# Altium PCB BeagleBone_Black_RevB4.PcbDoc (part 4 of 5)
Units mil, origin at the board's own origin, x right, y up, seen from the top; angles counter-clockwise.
Board outline 3401 x 2151 mil, 6 copper layers (TOP, LYR2_GND, LYR3, LYR4, LYR5_PWR, BOTTOM), stack 62 mil thick; 381 components, 310 nets, 1705 pads, 850 vias.
Unrouted connection lines stored in the file: 1.
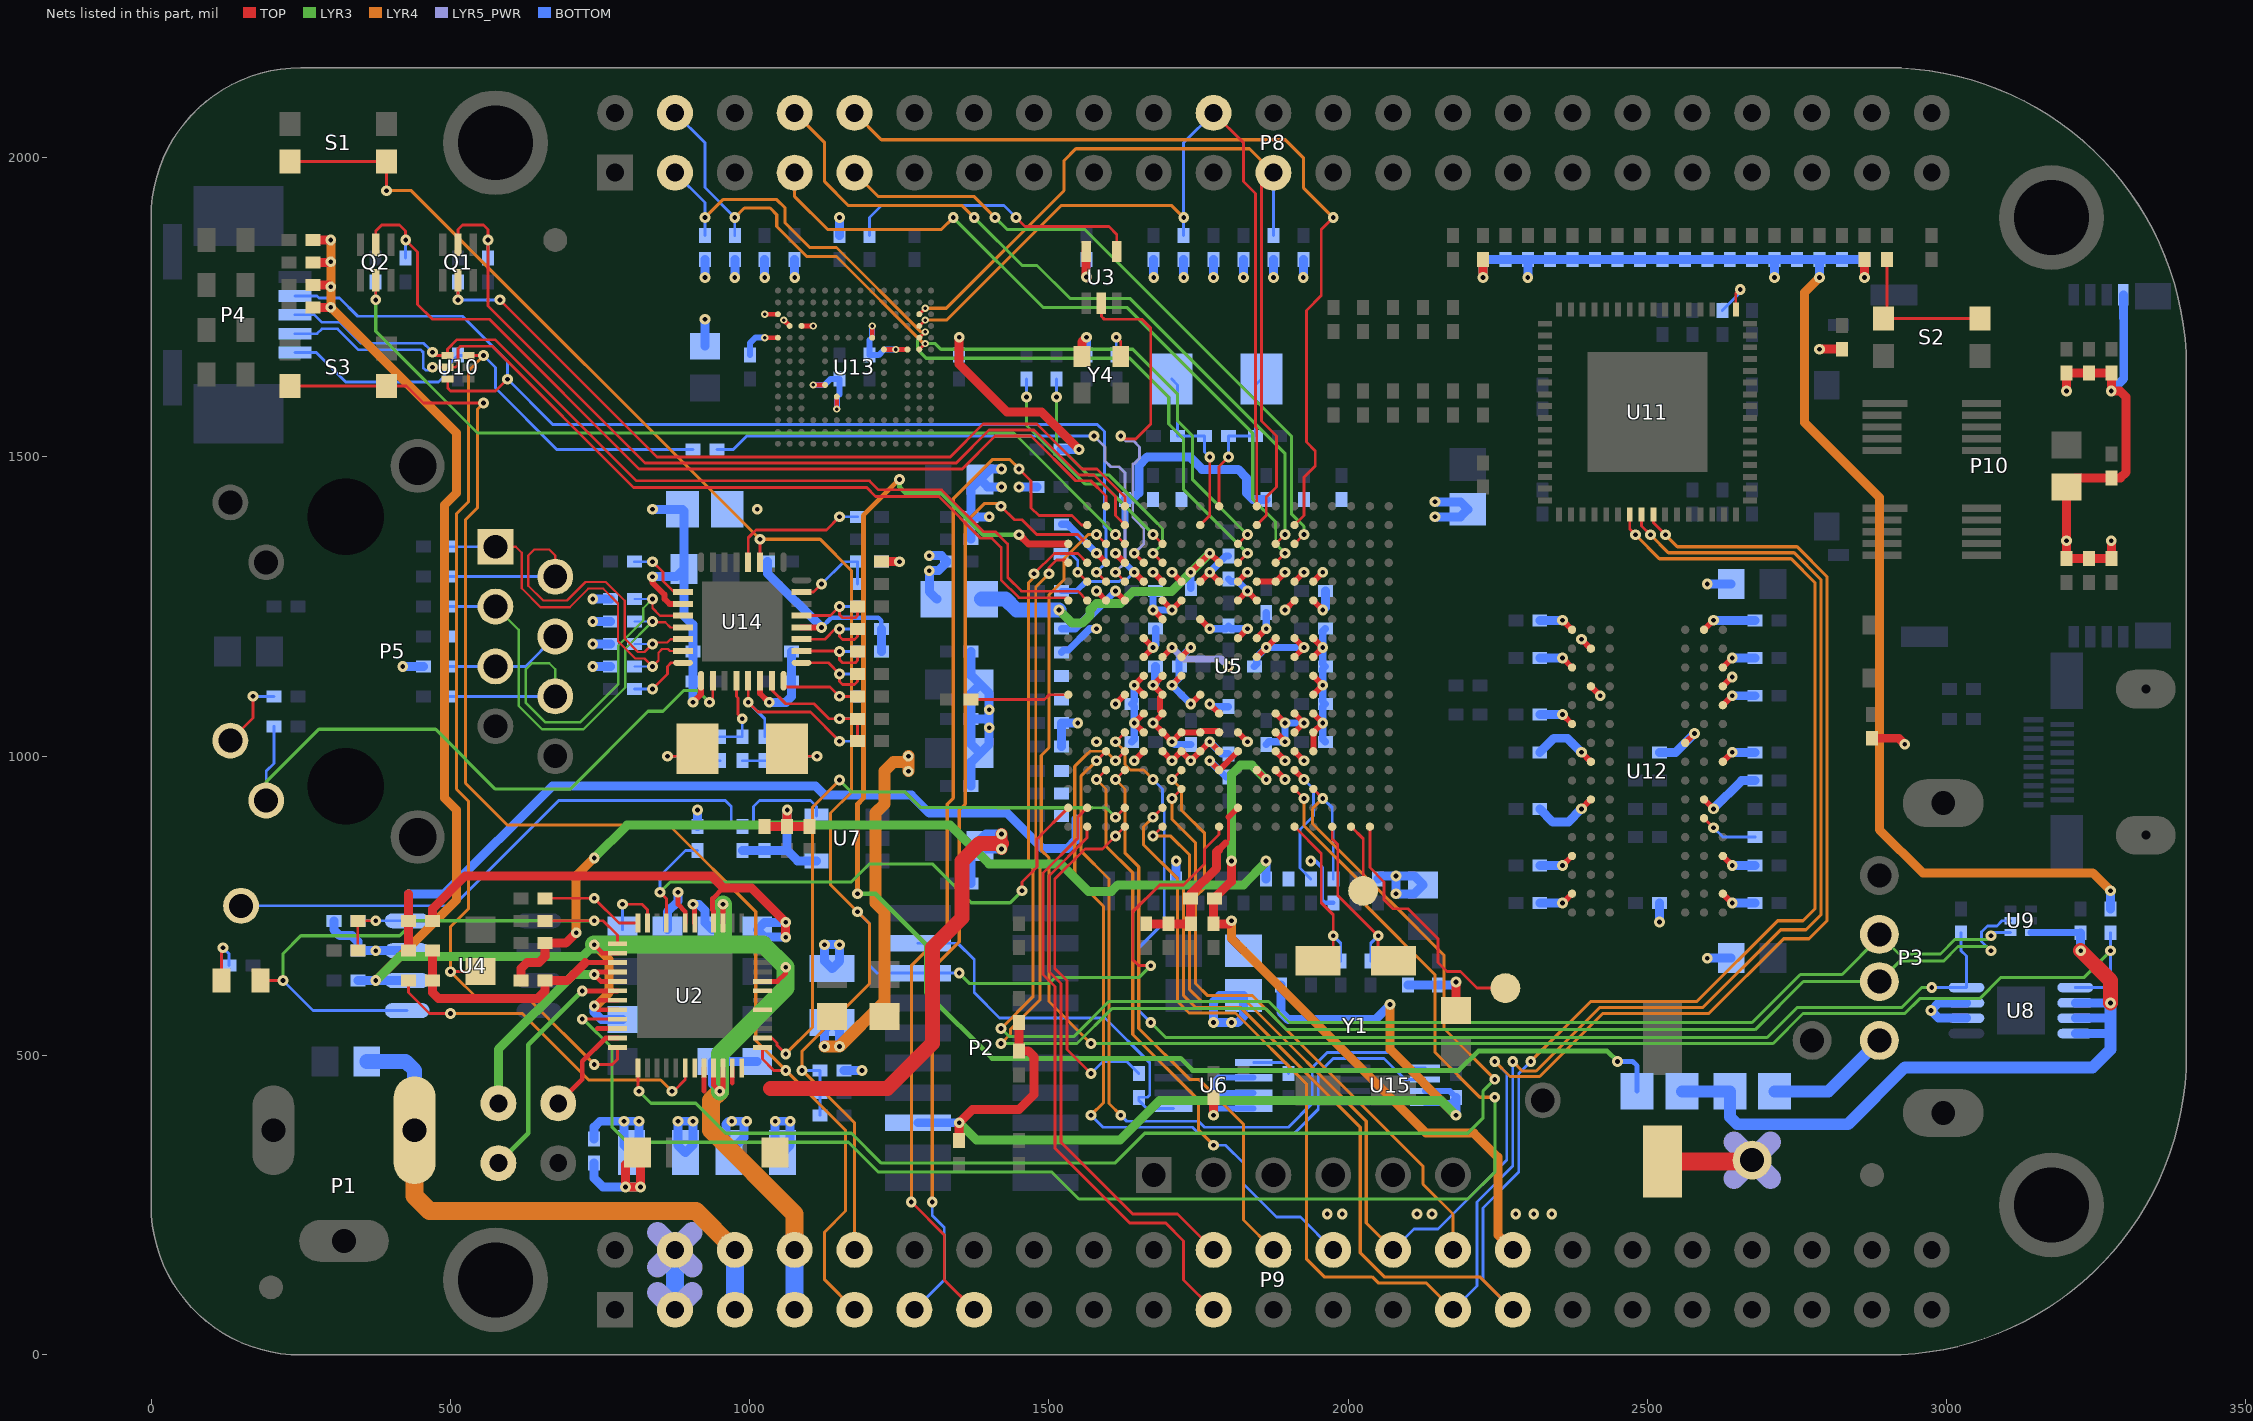
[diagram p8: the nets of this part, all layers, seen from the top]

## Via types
v1: diameter 18, hole 8, TOP to BOTTOM, tented both sides, 793 vias
v2: diameter 22, hole 12, TOP to BOTTOM, tented both sides, 30 vias
v3: diameter 12, hole 6, TOP to BOTTOM, tented both sides, 27 vias

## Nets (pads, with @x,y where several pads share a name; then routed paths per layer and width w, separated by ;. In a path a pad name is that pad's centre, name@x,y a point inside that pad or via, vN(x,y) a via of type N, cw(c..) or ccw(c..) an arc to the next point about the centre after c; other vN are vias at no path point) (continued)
MMC1_DAT4: P8.23 R105.2 U5.U8 U13.B3 | length 1478.1
  TOP w4.75: U13.B3@1283.27,1738.58 v3(1293.11,1748.43) ; U5.U8@1847.24,1386.22 1863.01,1401.99 1863.01,1433.01 1880,1450 1880,1535 1855,1560 1855,1955 P8.23@1875,1975
  LYR4 w5.25: v3(1293.11,1748.43) 1328.43,1748.43 1525,1945 1525,1995 1545,2015 1835,2015 P8.23@1875,1975
  BOTTOM w4.75: R105.2@1875,1870 P8.23@1875,1975
MMC1_DAT5: P8.22 R106.2 U5.V8 U13.B4 | length 1446.2
  TOP w4.75: U13.B4@1283.27,1718.9 v3(1293.11,1728.74) ; P8.22@1775,2075 1825,2025 1825,1960 1845,1940 1845,1550 1847.24,1547.76 U5.V8@1847.24,1417.72
  LYR4 w5.25: v3(1293.11,1728.74) 1328.74,1728.74 1520,1920 1705,1920 v1(1725,1900)
  BOTTOM w4.75: R106.2@1725,1870 v1(1725,1900) 1725,2025 P8.22@1775,2075
MMC1_DAT6: P8.3 R107.2 U5.R9 U13.B5 | length 1451.7
  TOP w4.75: U13.B5@1283.27,1699.21 v3(1293.11,1709.06) ; U5.R9@1815.75,1323.23 v1(1831.5,1338.98)
  LYR3 w5.25: v3(1293.11,1709.06) 1280,1695.95 1280,1680 1295,1665 1635,1665 1700,1600 1700,1555 1725,1530 1725,1445.48 v1(1831.5,1338.98)
  LYR4 w5.25: v1(925,1900) 955,1930 1045,1930 1059.01,1915.99 1059.01,1890.99 1100,1850 1145,1850 1285.94,1709.06 v3(1293.11,1709.06)
  BOTTOM w4.75: P8.3@875,1975 925,1925 v1(925,1900) R107.2@925,1870
MMC1_DAT7: P8.4 R108.2 U5.T9 U13.B6 | length 1452.6
  TOP w4.75: U13.B6@1283.27,1679.53 v3(1293.11,1689.37) ; U5.T9@1815.75,1354.72 v1(1831.5,1370.47)
  LYR3 w5.25: v3(1293.11,1689.37) 1310,1689.37 1319.37,1680 1640,1680 1715,1605 1715,1560 1740,1535 1740,1461.97 v1(1831.5,1370.47)
  LYR4 w5.25: v1(975,1900) 990.99,1915.99 1034.01,1915.99 1045,1905 1045,1885 1095,1835 1145,1835 1290.63,1689.37 v3(1293.11,1689.37)
  BOTTOM w4.75: P8.4@875,2075 925,2025 925,1950 v1(975,1900) R108.2@975,1870
MODE2: R113.1 R138.2 U14.15 | length 152
  TOP w4.75: U14.15@1086.5,1274.25 1106.75,1274.25 v1(1120,1287.5)
  BOTTOM w4.75: v1(1120,1287.5) 1157.5,1325 R113.1@1180,1325 R138.2@1180,1287.5
NetC19_1: C19.1 R10.1 R11.2 U4.4 | length 162.5
  TOP w4.75: R10.1@345,675 C19.1@345,725 v1(375,725)
  BOTTOM w4.75: R11.2@345,725 v1(375,725) U4.4@427.5,725
NetR21_1: R21.1 U6.5 | length 73.5
  BOTTOM w4.75: U6.5@1842,488.4 1895,488.4 1900,483.4 R21.1@1900,470
NetR75_2: R75.2 S2.1 S2.3 | length 262.3
  TOP w4.75: R75.2@2900,1830 2900,1737.21 S2.3@2894.29,1731.5 S2.1@3055.71,1731.5
NetR149_1: R149.1 U11.49 | length 84.2
  TOP w4.75: U11.49@2647.64,1746.26 2647.64,1772.64 v1(2655,1780)
  BOTTOM w4.75: R149.1@2625,1745 2655,1775 v1(2655,1780)
NetR159_2: R159.2 U5.P15 | length 925
  TOP w4.75: v1(1611,1307.5) U5.P15@1626.77,1291.73
  LYR5_PWR w4.75: v1(1575,1535) 1593.62,1516.38 1593.62,1493.22 1603.22,1483.62 1616.78,1483.62 1626.74,1473.66 1626.74,1323.24 v1(1611,1307.5)
  BOTTOM w4.75: R159.2@945,1512.5 972.5,1512.5 995,1535 v1(1575,1535)
NetR162_1: R162.1 U3.4 | length 499.9
  TOP w4.75: v1(1445,1900) 1460,1885 1600,1885 1613.09,1871.91 U3.4@1613.09,1843.31
  BOTTOM w4.75: R162.1@1200,1870 1200,1900 1220,1920 1425,1920 v1(1445,1900)
NetR167_1: R167.1 Y4.3 | length 65.1
  TOP w4.75: v1(1612.5,1700) 1620,1692.5 Y4.3@1620,1668
  BOTTOM w4.75: R167.1@1612.5,1670 v1(1612.5,1700)
NetTP5_1: TP5.1 U2.4 U2.5 | length 386.2
  TOP w8: U2.5@778.94,623.62 751.38,623.62 v1(740,635) 744.37,639.37 U2.4@778.94,639.37
  LYR3 w15: TP5.1@580,420 580,510 705,635 v1(740,635)
NetTP6_1: TP6.1 U2.6 | length 404.8
  TOP w8: v1(720,607.87) U2.6@778.94,607.87
  LYR3 w8: TP6.1@580,320 630,370 630,517.87 v1(720,607.87)
NetTP7_1: TP7.1 U2.11 | length 161.7
  TOP w8: TP7.1@680,420 720,460 720,490 759.13,529.13 U2.11@778.94,529.13
NetU3_2: U3.2 U5.R14 | length 593.9
  TOP w4.75: U3.2@1587.5,1756.69 1587.5,1734.75 1592.25,1730 1655,1730 1670,1715 1670,1555 1645,1530 1625,1530 v1(1620,1535) ; v1(1642.5,1339) U5.R14@1658.27,1323.23
  LYR5_PWR w4.75: v1(1620,1535) 1628.62,1526.38 1641.78,1526.38 1651.38,1516.78 1651.38,1498.22 1641.78,1488.62 1640,1488.62 1640,1400 1658.26,1381.74 1658.26,1354.76 v1(1642.5,1339)
OSC0_IN: C25.1 R17.1 U5.V10 Y2.2 | length 267.9
  TOP w4.75: U5.V10@1784.25,1417.72 1784.25,1484.25 v1(1800,1500)
  BOTTOM w4.75: v1(1800,1500) R17.1@1799.96,1535 C25.1@1845,1535 1845,1620.2 Y2.2@1854.8,1630
OSC0_OUT: C26.1 R17.2 U5.U11 Y2.1 | length 302.9
  TOP w4.75: U5.U11@1752.76,1386.22 1768.52,1401.98 v1(1768.52,1500)
  BOTTOM w4.75: Y2.1@1705.2,1630 1715,1620.2 C26.1@1715,1535 R17.2@1759.96,1535 1760,1508.52 v1(1768.52,1500)
OSC1_IN: C21.2 U5.A6 Y1.1 | length 318.6
  TOP w4.75: U5.A6@1910.24,882.28 1955,837.52 1955,755 1975,735 v1(1975,700) 1975,667.5 1965.7,658.2 Y1.1@1949.5,658.2
  BOTTOM w4.75: v1(1975,700) 1987.5,687.5 C21.2@1987.5,657.5
OSC1_OUT: C22.2 U5.A4 Y1.4 | length 323.6
  TOP w4.75: U5.A4@1973.23,882.28 1973.23,861.77 1982.5,852.5 1982.5,767.5 v1(2050,700) 2050,667.5 2059.3,658.2 Y1.4@2075.5,658.2
  BOTTOM w4.75: C22.2@2037.5,657.5 2037.5,687.5 v1(2050,700)
P_BYPASS: C4.2 U2.47 | length 110.2
  TOP w4.75: v1(787.5,752.5) 820,752.5 829.13,743.37 U2.47@829.13,721.06
  BOTTOM w4.75: C4.2@787.5,710 v1(787.5,752.5)
P_INT_LDO: C3.2 U2.48 | length 173.1
  TOP w4.75: C3.2@657.5,762.5 v1(740,762.5) 781.44,721.06 U2.48@813.39,721.06
P_L1: L1.1 U2.20 | length 179.3
  TOP w8: 923.62,440 U2.20@923.62,478.94
  BOTTOM w15: L1.1@880,350 v1(880,390) v1(905,390) 905,350 L1.1@892.5,337.5 L1.1@880,350
P_L2: L2.1 U2.23 | length 176.4
  TOP w8: 970.87,454.13 U2.23@970.87,478.94
  BOTTOM w15: L2.1@960,342.5 960,385 965,390 v1(970,390) v1(995,390) 990,385 990,362.5 L2.1@965,337.5 L2.1@960,342.5
P_L3: L3.1 U2.31 | length 115.4
  BOTTOM w15: L3.1@1125,657.5 v1(1125,685) v1(1150,685) 1150,657.5 L3.1@1137.5,645 L3.1@1125,657.5
PHY_VDDCR: C134.1 C136.1 U14.6 | length 159.6
  TOP w10: U14.6@1017.05,1126 1017.05,1104.83 1031.88,1090 v1(1032.5,1090)
  BOTTOM w15: v1(1032.5,1090) 1060.25,1090 1070,1099.75 C134.1@1070,1125 C136.1@1070,1175
PHY_XTAL1: C143.1 R141.2 R142.1 Y3.1 | length 183.5
  TOP w4.75: Y3.1@1062.3,1012.5 1074.8,1000 v1(1112.5,1000)
  BOTTOM w4.75: R141.2@987.5,992.5 R142.1@1025,992.5 C143.1@1062.5,992.5 1070,1000 v1(1112.5,1000)
PHY_XTAL2: R141.1 R143.1 U14.4 | length 135.1
  TOP w4.75: U14.4@977.65,1126 977.65,1099.85 980.15,1097.35 980.15,1069.85 v1(987.5,1062.5)
  BOTTOM w4.75: R143.1@950,1032.5 R141.1@987.5,1032.5 v1(987.5,1062.5)
PHYX: C142.1 R143.2 Y3.2 | length 146
  TOP w4.75: v1(862.5,1000) 900.2,1000 Y3.2@912.7,1012.5
  BOTTOM w4.75: v1(862.5,1000) 905,1000 C142.1@912.5,992.5 R143.2@950,992.5
PMIC_INT: R1.2 U2.45 U5.B18 | length 994.1
  TOP w4.75: v1(850,772.5) 860.63,761.87 U2.45@860.63,721.06 ; v1(1455,775) 1455,790 1480,815 1480,861.5 U5.B18@1532.28,913.78
  LYR3 w5.25: v1(850,772.5) 867.5,790 1170,790 1200,820 1305,820 1370,755 1435,755 v1(1455,775)
  BOTTOM w4.75: v1(850,772.5) 850,800 892.5,842.5 R1.2@912.5,842.5
PMIC_PGOOD: U2.26 U5.B15 | length 1056.1
  TOP w4.75: U2.26@1021.06,529.13 1037.35,529.13 1045.54,520.94 1045.54,516.96 v1(1060,502.5) ; v1(1611,898) U5.B15@1626.77,913.78
  LYR3 w4.75: 1572.64,913.74 1595.26,913.74 v1(1611,898)
  LYR3 w5.25: v1(1150,960) 1170,940 1260,940 1285.99,914.01 1413.74,914.01 1414.01,913.74 1572.64,913.74
  LYR4 w5.25: v1(1060,502.5) 1105,547.5 1105,915 v1(1150,960)
PMIC_POWR_EN: U2.9 U5.C6 | length 2598.3
  TOP w4.75: v1(720,560.63) U2.9@778.94,560.63 ; U5.C6@1910.24,945.28 v1(1926,929.5)
  LYR3 w5.25: v1(720,560.63) 721.87,560.63 770,512.5 770,380 795,355 1165,355 1215,305 1505,305 1550,260 2200,260 2245,305 v1(2245,430)
  LYR4 w5.25: v1(1926,929.5) 1926,884 2030,780 2030,750 2145,635 2145,505 2220,430 v1(2245,430)
PROC_A15: R18.1 U5.A15 | length 599.8
  TOP w4.75: v1(1570,470) 1530,510 1530,625 1509.51,645.49 1509.51,794.51 1560,845 1589.5,845 v1(1611,866.5) U5.A15@1626.77,882.28
  BOTTOM w4.75: v1(1570,470) 1590,490 1630,490 R18.1@1650,470
PWR_BUT: P9.9 S3.2 S3.4 U2.25 | length 2385.1
  TOP w4.75: S3.4@231.79,1618.5 S3.2@393.21,1618.5 426.5,1618.5 455,1590 v1(555,1590) ; U2.25@1021.06,513.39 1021.06,493.94 1040,475 v1(1060,475)
  LYR4 w5.25: v1(555,1590) 545,1580 545,1415 525,1395 525,955 595,885 865,885 1010,740 1010,525 v1(1060,475) 1160,375 1160,240 1125,205 1125,125 P9.9@1175,75
PWR_LEDR: D1.1 R12.2 | length 90.2
  TOP w4.75: D1.1@117.5,625 117.5,677.5 v1(120,680)
  BOTTOM w4.75: v1(120,680) 130,670 R12.2@130,650
RBIAS: R144.1 U14.32 | length 106.4
  TOP w4.75: v1(837.5,1112.5) 862.5,1137.5 862.5,1150 868.55,1156.05 U14.32@888.5,1156.05
  BOTTOM w4.75: R144.1@807.5,1112.5 v1(837.5,1112.5)
RCLKIN: R140.2 R142.2 U14.5 | length 314.4
  TOP w4.75: U14.5@997.35,1126 997.35,1100.15 997.5,1100 v1(997.5,1090) 1013.88,1073.62 1101.38,1073.62 v1(1150,1025)
  BOTTOM w4.75: v1(997.5,1090) 1025,1062.5 R142.2@1025,1032.5 ; v1(1150,1025) R140.2@1180,1025
REFCLKO: R118.1 R124.2 R131.2 U14.7 | length 246
  TOP w4.75: U14.7@1036.75,1126 1036.75,1110.75 1060,1087.5 1107.5,1087.5 1132.5,1062.5 v1(1150,1062.5) R124.2@1180,1062.5 R118.1@1180,1025
  BOTTOM w4.75: v1(1150,1062.5) R131.2@1180,1062.5
RXD0/MODE0: R112.1 R128.2 U14.11 | length 159.7
  TOP w4.75: U14.11@1086.5,1195.45 1125.45,1195.45 1142.5,1212.5 v1(1150,1212.5) 1150,1200 1155,1195 1175,1195 1180,1200 R128.2@1180,1212.5
  BOTTOM w4.75: v1(1150,1212.5) R112.1@1180,1212.5
RXD1/MODE1: R114.1 R127.2 U14.10 | length 156.2
  TOP w4.75: U14.10@1086.5,1175.75 1137.5,1175.75 1149.39,1175.61 v1(1150,1175) 1150,1161.23 1155,1156.23 1176.23,1156.23 1180,1160 R127.2@1180,1175
  BOTTOM w4.75: v1(1150,1175) R114.1@1180,1175
RXD2/RMIISEL: R117.1 R126.2 U14.9 | length 160.3
  TOP w4.75: U14.9@1086.5,1156.05 1131.45,1156.05 v1(1150,1137.5) 1150,1125 1155,1120 1175,1120 1180,1125 R126.2@1180,1137.5
  BOTTOM w4.75: v1(1150,1137.5) R117.1@1180,1137.5
RXD3/PHYAD2: R116.1 R125.2 U14.8 | length 167.4
  TOP w4.75: U14.8@1056.45,1126 1056.45,1120.74 1061.45,1115.74 1134.26,1115.74 v1(1150,1100) R125.2@1180,1100
  BOTTOM w4.75: v1(1150,1100) R116.1@1180,1100
RXDV: R129.2 U14.26 | length 110.8
  TOP w4.75: v1(837.5,1325) 855,1307.5 855,1292.5 873.25,1274.25 U14.26@888.5,1274.25
  BOTTOM w4.75: R129.2@807.5,1325 v1(837.5,1325)
RXER/PHYAD0: R115.1 R133.2 U14.13 | length 162.2
  TOP w4.75: U14.13@1086.5,1234.85 1134.85,1234.85 v1(1150,1250) 1150,1236.23 1155,1231.23 1176.23,1231.23 1180,1235 R133.2@1180,1250
  BOTTOM w4.75: v1(1150,1250) R115.1@1180,1250
RXN: C138.1 P5.2 R121.1 U14.30 | length 724.8
  TOP w3.75: P5.2@675,1300 675,1335.39 665,1345.39 640,1345.39 630,1335.39 630,1285 655,1260 694.44,1260 725.44,1291 759.56,1291 791,1259.56 791,1196.5 813.25,1174.25 824.25,1174.25 v1(837.5,1187.5) 840,1190 862.05,1190 867.5,1195.45 U14.30@888.5,1195.45
  BOTTOM w3.75: R121.1@807.5,1187.5 v1(837.5,1187.5)
  BOTTOM w4.75: C138.1@495,1300 P5.2@675,1300
RXP: C137.1 P5.1 R120.1 U14.31 | length 624.8
  TOP w3.75: P5.1@575,1350 609,1350 619,1340 619,1280.44 650.44,1249 699,1249 730,1280 755,1280 780,1255 780,1191.94 808.69,1163.25 824.25,1163.25 v1(837.5,1150) 847.5,1160 847.5,1173 853.5,1179 863.5,1179 866.75,1175.75 U14.31@888.5,1175.75
  BOTTOM w3.75: R120.1@807.5,1150 v1(837.5,1150)
  BOTTOM w4.75: C137.1@495,1350 P5.1@575,1350
SPI1_CS0: P9.28 U5.C12 U11.25 | length 2996.8
  TOP w4.75: v1(1705.5,929.5) U5.C12@1721.26,945.28 ; U11.25@2509.84,1403.74 2509.84,1390.16 v1(2530,1370)
  LYR4 w5.25: v1(1705.5,929.5) 1705.5,894.5 1745,855 1745,785 1735,775 1735,610 1755,590 1830,590 2030,390 2030,220 P9.28@2075,175 ; v1(2245,490) 2270.24,464.76 2319.76,464.76 2425,570 2602.5,570 2727.5,695 2770,695 2800,725 2800,1300 2750,1350 2550,1350 v1(2530,1370)
  BOTTOM w4.75: P9.28@2075,175 2110,210 2150.01,210 2265,324.99 2265,470 v1(2245,490)
SPI1_D0: P9.29 U5.B13 U11.24 | length 3207.4
  TOP w4.75: v1(1674,898) U5.B13@1689.76,913.78 ; U11.24@2490.16,1403.74 2490.16,1384.84 v1(2505,1370)
  LYR4 w5.25: v1(1674,898) 1658.01,882.01 1658.01,851.99 1715,795 1715,590 1734.01,570.99 1811.62,570.99 1930,452.61 1930,160 1960,130 2040,130 2050,120 2130,120 P9.29@2175,75 ; v1(2275,490) 2290.99,474.01 2314.01,474.01 2420,580 2592.5,580 2722.5,710 2765,710 2790,735 2790,1295 2745,1340 2535,1340 v1(2505,1370)
  BOTTOM w4.75: P9.29@2175,75 2215,115 2215,255 2275,315 v1(2275,490)
SPI1_D1: P9.30 U5.D12 | length 1059.3
  TOP w4.75: v1(1705.5,961) U5.D12@1721.26,976.77
  LYR4 w4.75: v1(1705.5,961) 1721.24,945.26 1721.24,910
  LYR4 w5.25: 1721.24,910 1760,871.24 1760,780 1744.75,764.75 1744.75,620.25 1765,600 1840,600 2125,315 2125,285 2175,235 P9.30@2175,175
SPI1_SCLK: P9.31 U5.A13 U11.23 | length 3191.3
  TOP w4.75: v1(1674,866.5) U5.A13@1689.76,882.28 ; U11.23@2470.47,1403.74 2470.47,1379.53 v1(2480,1370)
  LYR4 w5.25: v1(1674,866.5) 1703.5,866.5 1735,835 1735,795 1725,785 1725,600 1744.76,580.24 1819.76,580.24 2020,380 2020,170 2060,130 2220,130 P9.31@2275,75 ; v1(2305,490) 2405,590 2582.5,590 2717.5,725 2760,725 2780,745 2780,1290 2740,1330 2520,1330 v1(2480,1370)
  BOTTOM w4.75: P9.31@2275,75 2225,125 2225,245 2285,305 2285,470 v1(2305,490)
SYS_5V: C7.2 C8.2 C10.2 C13.2 C17.1 C34.1 P9.7 P9.8 R71.1 R72.1 R73.1 R74.1 RT1.1 U2.2 U2.7 U2.8 U2.21 U2.22 U2.32 U2.39 U2.42 U4.2 U8.2 U8.3 | length 4290.6
  TOP w8: v1(740,685) 754.13,670.87 U2.2@778.94,670.87 ; U2.8@778.94,576.38 746.12,576.38 v1(740,582.5) 749.63,592.13 U2.7@778.94,592.13 ; v1(905,752.5) 907.87,748.08 U2.42@907.87,721.06 ; U2.21@939.37,478.94 939.37,450.63 v1(950,440) 955.12,445.12 U2.22@955.12,478.94 ; U2.39@955.12,721.06 v1(955.12,752.5) ; U2.32@1021.06,623.62 1046.12,623.62 1060,637.5 v1(1060,647.5)
  TOP w15: R71.1@270,1750 v1(300,1750) ; R74.1@270,1787.5 296.97,1787.5 v1(300,1784.47) ; R73.1@270,1825 298.81,1825 v1(300,1826.19) ; R72.1@270,1862.5 v1(300,1862.5)
  TOP w30: C34.1@2525,322.5 2672.5,322.5 RT1.1@2675,325
  LYR3 w15: v1(375,625) 415,665 720,665 v1(740,685)
  LYR3 w30: v1(740,685) 955.12,685 ; v1(950,440) 950,502.5 1060,612.5 v1(1060,647.5) 1022.5,685 955.12,685 ; v1(955.12,752.5) 955.12,685
  LYR4 w15: v1(300,1862.5) v1(300,1826.19) v1(300,1784.47) v1(300,1750) 510,1540 510,1440 490,1420 490,930 510,910 510,760 v1(375,625) ; v1(740,582.5) 742.5,582.5 765,605 765,660 v1(740,685)
  LYR4 w30: v1(950,440) 935,425 935,375 1075,235 P9.8@1075,175
  LYR5_PWR w35: 2644.35,294.35 RT1.1@2675,325 ; 2644.35,355.65 RT1.1@2675,325 ; 2705.65,294.35 RT1.1@2675,325 ; 2705.65,355.65 RT1.1@2675,325
  BOTTOM w15: C17.1@345,625 v1(375,625) U4.2@427.5,625 ; v1(740,582.5) 740,572.5 752.5,560 C10.2@787.5,560 ; v1(905,752.5) 915,752.5 925,742.5 925,722.5 C13.2@937.5,710 955.12,727.62 v1(955.12,752.5) ; v1(950,440) 937.5,452.5 C7.2@937.5,490 C8.2@1012.5,490 ; U8.2@3032.9,562.2 2986.7,562.2 v1(2973.9,575) 2986.7,587.8 U8.3@3032.9,587.8
  BOTTOM w30: P9.7@1075,75 P9.8@1075,175
SYS_RESETN: C24.1 C30.1 P2.15 P9.10 R14.2 S1.2 S1.4 U5.A10 U14.19 | length 3585.2
  TOP w4.75: S1.4@231.79,1993.5 S1.2@393.21,1993.5 v1(393.21,1945) ; U14.19@1017.05,1324 v1(1017.05,1362.5) ; v1(1670,650) 1650,650 1640,660 1640,740 1685,785 1725,785 1760,820 1760,845 1784.25,869.25 U5.A10@1784.25,882.28
  LYR3 w5.25: v1(1350,637.5) 1367.5,620 1500,620 1510,630 1650,630 v1(1670,650)
  LYR4 w5.25: v1(393.21,1945) 434.55,1945 v1(1017.05,1362.5) 1117.52,1362.5 1170,1310 1170,940 1135,905 1135,785 v1(1180,740) 1200,720 1200,620 1087.5,507.5 v1(1087.5,475) 1175,387.5 P9.10@1175,175
  BOTTOM w4.75: v1(1087.5,475) R14.2@1117.5,475 C24.1@1117.5,437.5 C30.1@1117.5,400 ; v1(1180,740) 1200,720 1200,650 1212.5,637.5 P2.15@1281,637.5 v1(1350,637.5)
TCT_RCT: C141.1 P5.4 P5.5 R137.1 | length 250.7
  BOTTOM w4.75: C141.1@495,1200 R137.1@495,1150 P5.5@575,1150 625,1150 P5.4@675,1200
TESTOUT: TP3.1 U5.A3 | length 115.7
  TOP w4.75: U5.A3@2004.72,882.28 2025,862 TP3.1@2025,775
TIMER4: P8.7 U5.R7 | length 1231.1
  TOP w4.75: U5.R7@1878.74,1323.23 v1(1894.5,1339)
  LYR3 w4.75: 1878.76,1380 1878.76,1354.74 v1(1894.5,1339)
  LYR3 w5.25: v1(1340,1900) 1490,1750 1630,1750 1840.5,1539.5 1840.5,1429.5 1878.76,1391.24 1878.76,1380
  LYR4 w5.25: P8.7@1075,1975 1075,1935 1130,1880 1320,1880 v1(1340,1900)
TIMER5: P8.9 U5.T6 | length 1107.8
  TOP w4.75: U5.T6@1910.24,1354.72 v1(1926,1370.5)
  LYR3 w5.25: v1(1410,1900) 1430,1880 1560,1880 1905,1535 1905,1405 1926,1384 v1(1926,1370.5)
  LYR4 w5.25: P8.9@1175,1975 1215,1935 1375,1935 v1(1410,1900)
TIMER6: P8.10 U5.U6 | length 1454.8
  TOP w4.75: U5.U6@1910.24,1386.22 1925.97,1401.95 1925.97,1465.97 1945,1485 1945,1510 1930,1525 1930,1745 1955,1770 1955,1880 v1(1975,1900)
  LYR4 w5.25: P8.10@1175,2075 1220,2030 1895,2030 1925,2000 1925,1950 v1(1975,1900)
TIMER7: P8.8 U5.T7 | length 1250.8
  TOP w4.75: U5.T7@1878.74,1354.72 v1(1894.5,1370.5)
  LYR3 w5.25: v1(1375,1900) 1455,1820 1480,1820 1535,1765 1635,1765 1894.5,1505.5 v1(1894.5,1370.5)
  LYR4 w5.25: P8.8@1075,2075 1125,2025 1125,1960 1165,1920 1355,1920 v1(1375,1900)
TXCLK: R134.2 U14.20 | length 238.2
  TOP w4.75: U14.20@997.35,1324 997.35,1365.06 1010.53,1378.24 1128.24,1378.24 v1(1150,1400)
  BOTTOM w4.75: v1(1150,1400) R134.2@1180,1400
TXN: C140.1 P5.6 R123.1 U14.28 | length 799.6
  TOP w3.75: v1(837.5,1262.5) 837.5,1247.46 850.11,1234.85 U14.28@888.5,1234.85
  LYR3 w4: P5.6@675,1100 675,1145.2 665,1155.2 636,1155.2 626,1145.2 626,1089 658,1057 717,1057 780,1120 780,1184.48 822.14,1226.62 822.14,1247.14 v1(837.5,1262.5)
  BOTTOM w3.75: R123.1@807.5,1262.5 v1(837.5,1262.5)
  BOTTOM w4.75: C140.1@495,1100 P5.6@675,1100
TXP: C139.1 P5.3 R122.1 U14.29 | length 699.6
  TOP w3.75: v1(837.5,1225) 837.49,1224.3 837.94,1223.85 858.8,1223.85 867.5,1215.15 U14.29@888.5,1215.15
  LYR3 w4: P5.3@575,1250 614,1211 614,1084.02 653.02,1045 721.98,1045 792,1115.02 792,1179.5 v1(837.5,1225)
  BOTTOM w3.75: R122.1@807.5,1225 v1(837.5,1225)
  BOTTOM w4.75: C139.1@495,1250 P5.3@575,1250
U5_H18: R28.1 U5.H18 | length 165.5
  TOP w4.75: R28.1@1370,1095 1492.24,1095 1500,1102.76 U5.H18@1532.28,1102.76
U5_R13: R160.1 U5.R13 | length 413.8
  TOP w4.75: v1(1673.99,1339) U5.R13@1689.76,1323.23
  LYR3 w4.75: v1(1673.99,1339) 1689.76,1354.77 1689.76,1380.24 1675,1395
  LYR3 w5.25: v1(1512.5,1600) 1512.5,1522.5 1565,1470 1600,1470 1675,1395
  BOTTOM w4.75: v1(1512.5,1600) R160.1@1512.5,1630
U5_T13: R161.1 U5.T13 | length 387
  TOP w4.75: v1(1674,1370.5) U5.T13@1689.76,1354.72
  LYR3 w5.25: v1(1462.5,1600) 1462.5,1552.5 1560,1455 1590,1455 1674,1371 v1(1674,1370.5)
  BOTTOM w4.75: v1(1462.5,1600) R161.1@1462.5,1630
UART0_RX: U5.E15 U15.6 | length 1390.8
  TOP w4.75: v1(1611,992.5) U5.E15@1626.77,1008.27
  LYR4 w4.75: 1565,1005 1568.24,1008.24 1595.26,1008.24 v1(1611,992.5)
  LYR4 w5.25: 1565,1005 1543.01,983.01 1543.01,796.99 1590.99,749.01 1590.99,421.03 v1(1570,400.04)
  BOTTOM w4.75: v1(1570,400.04) 1590,380 1740,380 1750,370 1910,370 1950,410 1950,470 1975,495 2060,495 2095.2,459.8 U15.6@2128,459.8
UART0_TX: U5.E16 U15.5 | length 1267.1
  TOP w4.75: v1(1579.5,992.5) U5.E16@1595.28,1008.27
  LYR4 w5.25: v1(1579.5,992.5) 1553.26,966.26 1553.26,841.74 1600.24,794.76 1600.24,419.76 v1(1620,400)
  BOTTOM w4.75: v1(1620,400) 1630,390 1750,390 1760,380 1900,380 1940,420 1940,480 1965,505 2070,505 2095.5,479.5 U15.5@2128,479.5
UART1_RXD: P9.26 U5.D16 | length 1007.3
  TOP w4.75: v1(1579.5,961) U5.D16@1595.28,976.77
  LYR4 w4.75: v1(1579.5,961) 1595.24,945.26 1595.24,855.24
  LYR4 w5.25: 1595.24,855.24 1595.24,849.76 1640,805 1640,535 1750,425 1750,375 v1(1775,350)
  BOTTOM w4.75: v1(1775,350) 1795,350 1825,320 1825,285 1880,230 1920,230 P9.26@1975,175
UART1_TXD: P9.24 U5.D15 | length 926.4
  TOP w4.75: v1(1611,961) U5.D15@1626.77,976.77
  LYR4 w4.75: v1(1611,961) 1626.74,945.26 1626.74,920
  LYR4 w5.25: 1626.74,920 1627.26,919.48 1627.26,837.74 1650,815 1650,545 1735,460 1750,460 1825,385 1825,225 P9.24@1875,175
UART2_RXD: P9.22 U5.A17 | length 891.7
  TOP w4.75: 1563.76,873.02 1563.76,863.76 1499.76,799.76 1499.76,640.24 1520,620 1520,355 1640,235 1715,235 P9.22@1775,175 ; 1563.78,873.04 U5.A17@1563.78,882.28
UART2_TXD: P9.21 U5.B17 | length 1022.5
  TOP w4.75: U5.B17@1563.78,913.78 1548.01,898.01 1548.01,863.01 1490,805 1490,635 1510,615 1510,345 1635,220 1695,220 1725,190 1725,125 P9.21@1775,75
UART4_RXD: P9.11 U5.T17 | length 1612.1
  TOP w4.75: v1(1420,1417.5) 1442.5,1395 1455,1395 1479.55,1370.45 1548.05,1370.45 U5.T17@1563.78,1354.72
  LYR4 w5.25: v1(1305,255) 1305,645 1350,690 1350,910 1360,920 1360,1390 1392.5,1422.5 1415,1422.5 v1(1420,1417.5)
  BOTTOM w4.75: P9.11@1275,75 1325,125 1325,212.5 1305,232.5 v1(1305,255)
UART4_TXD: P9.13 U5.U17 | length 1750.4
  TOP w4.75: v1(1270,255) 1325,200 1325,125 P9.13@1375,75 ; v1(1450,1480) 1470,1460 1470,1415 1483.05,1401.95 1538.65,1401.95 1554.38,1386.22 U5.U17@1563.78,1386.22
  LYR4 w5.25: v1(1270,255) 1270,650 1330,710 1330,920 1340,930 1340,1430 1405.99,1495.99 1434.01,1495.99 v1(1450,1480)
USB0_DM: P4.2 U5.N18 U10.2 | length 1580
  TOP w4.5: v1(470,1650) U10.2@495.22,1650 508.5,1650 512.5,1654 512.5,1680.57 516.93,1685 570,1685 806,1449 1195.44,1449 1210.44,1434 1316,1434 1386,1364 1405,1364 1420,1349 1420,1294.44 1449.6,1264.84 1527.68,1264.84 U5.N18@1532.28,1260.24
  BOTTOM w4.5: P4.2@240,1706 277,1706 285,1714 311,1714 346,1679 450.39,1679 454.39,1675 454.39,1649 458.39,1645 466,1645 470,1649 v1(470,1650)
USB0_DP: P4.3 U5.N17 U10.1 | length 1582.2
  TOP w4.5: v1(470,1675) 475.32,1669.68 U10.1@495.22,1669.68 495,1669.9 495,1680 511,1696 574.56,1696 810.56,1460 1200,1460 1215,1445 1320.56,1445 1390.56,1375 1410.56,1375 1431,1354.56 1431,1299 1454.16,1275.84 1548.18,1275.84 U5.N17@1563.78,1260.24
  BOTTOM w4.5: P4.3@240,1737.5 272.5,1737.5 285,1725 315.56,1725 350.56,1690 454.95,1690 v1@465.39,1679.56 ; v1@465.44,1679.56 v1(470,1675)
USB0_ID: P4.4 U5.P16 U10.3 | length 1854.3
  TOP w4.75: U10.3@495.22,1630.32 495.22,1615 500.22,1610 575,1610 v1(595,1630) ; v1(1579.5,1307.5) U5.P16@1595.28,1291.73
  BOTTOM w4.75: P4.4@240,1769 276.74,1769 280,1765.74 314.26,1765.74 345,1735 520,1735 595,1660 v1(595,1630) 670.74,1554.26 1580.74,1554.26 1592.5,1542.5 1592.5,1382.5 1595.24,1379.76 1595.24,1323.24 v1(1579.5,1307.5)
USB1_DM: P3.2 U5.R18 U9.2 | length 2720.4
  TOP w4.5: v1(1500,1305) 1500,1315.03 1512.8,1327.83 1527.68,1327.83 U5.R18@1532.28,1323.23
  LYR3 w5: v1(1420,520) 1546.98,520 1604.98,578 1862,578 1897,543 2679.98,543 2760.38,623.4 P3.2@2887.5,623.4 2921.6,657.5 2994.48,657.5 3018.98,682 3066.9,682 v1(3073.9,675)
  LYR4 w5: v1(1420,520) 1435.86,535.86 1435.86,543.88 1485,593.02 1485,817.86 1477.86,825 1477.86,1282.86 v1(1500,1305)
  BOTTOM w4.5: v1(3073.9,675) 3058.29,690.61 3058.29,706.47 3068.14,716.32 3083.9,716.32 3092.58,725 U9.2@3106.62,725
USB1_DP: P3.3 U5.R17 U9.1 | length 2720.6
  TOP w4.5: v1(1475,1305) 1508.83,1338.83 1548.18,1338.83 U5.R17@1563.78,1323.23
  LYR3 w5: v1(1420,545) 1433,532 1542,532 1600,590 1866.98,590 1901.98,555 2675,555 2755.4,635.4 2825.4,635.4 2887.5,697.5 P3.3@2887.5,702.2 2920.2,669.5 2989.5,669.5 3014,694 3067.9,694 v1(3073.9,700)
  LYR4 w5: v1(1420,545) 1473,598 1473,812.88 1465.86,820.02 1465.86,1290 1475,1299.14 v1(1475,1305)
  BOTTOM w4.5: v1(3073.9,700) 3079.22,705.32 U9.1@3106.62,705.32
USB1_DRVVBUS: R53.1 U5.F15 U8.4 | length 2067.1
  TOP w4.75: v1(1611,1024) U5.F15@1626.77,1039.76
  LYR3 w5.25: v1(1670,555) 1695,530 2700,530 2750,580 2925,580 2958.4,613.4 v1(2975,613.4)
  LYR4 w4.75: v1(1611,1024) 1626.74,1008.26 1626.74,985.98 1635.98,976.74 1658.26,976.74 v1(1674,961)
  BOTTOM w4.75: v1(1670,555) 1650,575 1650,680 1692.5,722.5 1692.5,910 1689.76,912.74 1689.76,945.24 v1(1674,961) ; v1(2975,613.4) U8.4@3032.9,613.4 3032.9,666 3023.9,675 R53.1@3023.9,705
USB1_ID: R49.2 U5.P17 | length 74.2
  TOP w4.75: v1(1548,1307.5) 1550,1305.51 U5.P17@1563.78,1291.73
  BOTTOM w4.75: R49.2@1520,1337.5 1537.5,1337.5 1548,1327 v1(1548,1307.5)
USB1_OCN: R52.2 U5.T16 U8.5 | length 2865.6
  TOP w4.75: v1(1579.5,1370.5) U5.T16@1595.28,1354.72
  LYR3 w5.25: v1(1570,520) 2710,520 2760,570 2930,570 2955,595 3055,595 3090,630 3228.9,630 v1(3273.9,675)
  LYR4 w5.25: v1(1570,520) 1500,590 1500,830 1486.99,843.01 1486.99,1001.24 1500,1014.25 1500,1270 1525,1295 1525,1330 1565.5,1370.5 v1(1579.5,1370.5)
  BOTTOM w4.75: U8.5@3214.9,613.4 3262.3,613.4 3273.9,625 v1(3273.9,675) R52.2@3273.9,705
USB1_PWR: C35.1 FB7.1 FB8.2 U8.6 U8.7 U8.8 U9.6 | length 1290.4
  TOP w25: v1(3223.9,675) 3273.6,625.3 v1(3273.6,587.8)
  BOTTOM w12: U9.6@3141.18,705.32 3223.58,705.32 C35.1@3223.9,705
  BOTTOM w15: U8.8@3214.9,536.6 3273.6,536.6 ; U8.7@3214.9,562.2 3273.6,562.2 ; U8.6@3214.9,587.8 v1(3273.6,587.8) ; v1(3223.9,675) C35.1@3223.9,705
  BOTTOM w20: FB8.2@2557.4,440 FB7.1@2637.6,440 2637.6,397.4 2650,385 2835,385 2930,480 3243.9,480 3273.6,509.7 3273.6,536.6 3273.6,562.2 v1(3273.6,587.8)
USB1_VBUS: FB8.1 U5.T18 | length 2593.5
  TOP w12: v1(1450,1370) 1450.28,1370 1465.56,1354.72 U5.T18@1532.28,1354.72
  LYR3 w8: v1(1180,770) 1210,770 1295,685 1295,605 1405,495 1720,495 1740,475 2185,475 2217.36,507.36 2432.64,507.36 v1(2450,490) ; v1(1250,1462.5) 1250,1450 1260,1440 1320,1440 1390,1370 v1(1450,1370)
  LYR4 w8: v1(1180,770) 1180,920 1190,930 1190,1402.5 v1(1250,1462.5)
  BOTTOM w8: v1(2450,490) 2475,490 2482.6,482.4 FB8.1@2482.6,440
USB_DC: C1.2 C36.1 P4.1 R159.1 U2.12 U10.6 | length 2307.3
  TOP w4.75: v1(500,640) C1.2@550,640 ; U10.6@529.78,1669.68 554.68,1669.68 v1(555,1669.36) ; v1(740,485) 770.25,485 778.94,493.69 U2.12@778.94,513.39
  LYR4 w5.25: v1(555,1669.36) 530,1644.36 530,1425 510,1405 510,945 530,925 530,745 500,715 v1(500,640) 550,590 635,590 v1(740,485)
  BOTTOM w4.75: P4.1@240,1674.51 275.49,1674.51 325,1625 480,1625 490,1635 490,1647.5 C36.1@512.5,1670 512.82,1669.68 554.68,1669.68 v1(555,1669.36) 575,1649.36 575,1615 677.5,1512.5 R159.1@905,1512.5
USR0: Q1.2 R76.1 U5.V15 | length 1374.7
  TOP w4.75: v1(512.5,1762.5) Q1.2@512.5,1795.47 ; v1(582.5,1762.5) 845,1500 1335,1500 1390,1555 1480,1555 1555,1480 1580,1480 1626.77,1433.23 U5.V15@1626.77,1417.72
  BOTTOM w4.75: R76.1@512.5,1792.5 v1(512.5,1762.5) v1(582.5,1762.5)
USR1: Q1.5 R77.1 U5.U15 | length 1519.5
  TOP w4.75: Q1.5@512.5,1854.53 512.5,1880 520,1887.5 555,1887.5 562.5,1880 v1(562.5,1862.5) 562.5,1752.5 825,1490 1345,1490 1400,1545 1475,1545 1550,1470 1575,1470 1611.01,1433.99 1611.01,1401.98 U5.U15@1626.77,1386.22
  BOTTOM w4.75: R77.1@562.5,1832.5 v1(562.5,1862.5)
USR2: Q2.2 R78.1 U5.T15 | length 1514.4
  TOP w4.75: v1(375,1762.5) Q2.2@375,1795.47 ; v1(1611,1370.5) U5.T15@1626.77,1354.72
  LYR3 w5.25: v1(375,1762.5) 375,1710 545,1540 1441.5,1540 v1(1611,1370.5)
  BOTTOM w4.75: v1(375,1762.5) R78.1@375,1792.5
USR3: Q2.5 R79.1 U5.V16 | length 1587.5
  TOP w4.75: Q2.5@375,1854.53 375,1877.5 385,1887.5 415,1887.5 425,1877.5 v1(425,1862.5) 445,1842.5 445,1755 470,1730 565,1730 815,1480 1355,1480 1410,1535 1470,1535 1544.75,1460.25 1569.75,1460.25 1595.28,1434.72 U5.V16@1595.28,1417.72
  BOTTOM w4.75: R79.1@425,1832.5 v1(425,1862.5)
VBUS: FB7.2 P3.1 | length 210.3
  BOTTOM w20: FB7.2@2712.4,440 2802.5,440 P3.1@2887.5,525
VDCDC1: L1.2 R6.1 U2.19 | length 214.6
  BOTTOM w15: R6.1@740,360 740,380.25 749.75,390 v1(790,390) ; v1(790,390) v1(815,390) 815,350 L1.2@802.5,337.5 790,350 v1(790,390)
VDD_1V8: C14.2 C78.1 C86.1 C88.1 FB1.1 FB2.2 FB5.2 R9.2 U2.40 U5.D10 U5.E9 U5.N16 U5.R16 | length 1567.2
  TOP w8: U2.40@939.37,721.06 939.37,741.19 937.76,742.8 937.76,762.08 955.68,780
  TOP w10: v1(1579.5,1276) U5.N16@1595.28,1260.24 ; v1(1579.5,1339) U5.R16@1595.28,1323.23 ; v1(1768.5,992.5) U5.D10@1784.25,976.77 U5.E9@1815.75,1008.27
  TOP w15: R9.2@470,725 470,745 525,800 935.68,800 955.68,780 1002.5,780 v1(1060,722.5) v1(1060,697.5)
  LYR3 w15: v1(1060,697.5) v1(1060,722.5)
  BOTTOM w12: C86.1@1520.75,1387.5 1531,1387.5 v1(1579.5,1339) ; v1(1768.5,992.5) 1795.75,965.25 C88.1@1800,965.25
  BOTTOM w15: v1(1300,1335) 1320,1335 C78.1@1330,1325 1315,1310 v1(1300,1310) 1300,1275.1 FB1.1@1312.6,1262.5 ; v1(2145,1400) 2187.4,1400 FB5.2@2200,1412.6 2187.6,1425 v1(2145,1425) ; C14.2@1012.5,710 1025,697.5 v1(1060,697.5) v1(1060,722.5) 1025,722.5 C14.2@1012.5,710 ; v1(1775,555) 1775,590 1785.1,600.1 FB2.2@1825,600.1 1825,565 1815,555 v1(1805,555) v1(1775,555)
VDD_3V3A: C15.2 C27.1 C37.1 C38.1 C56.2 C57.2 C58.1 C59.1 C60.2 C61.2 C66.1 C67.1 C68.2 C69.2 C70.2 C71.2 C72.2 C73.2 C74.2 C75.2 C76.2 C77.1 C87.1 C152.1 C158.1 C159.1 R1.1 R3.1 R4.1 R14.1 R52.1 R55.1 R56.1 R57.1 R58.1 R59.1 R60.1 R61.1 R62.1 R63.1 R64.1 R65.1 R66.1 R67.1 R68.1 R69.1 R70.1 R156.1 U2.43 U3.5 U5.E10 U5.E11 U5.E12 U5.E13 U5.F14 U5.G14 U5.H14 U5.J14 U5.K14 U5.L14 U5.N5 U5.N15 U5.P5 U5.P6 U5.P7 U5.P8 U5.P10 U5.P11 U5.P12 U5.P13 U5.R15 U6.6 U6.7 U6.8 U7.4 Y4.4 | length 4369.5
  TOP w8: v1(880.25,772.62) 880.25,752.25 892.13,740.37 U2.43@892.13,721.06
  TOP w10: v1(1611,1276) U5.N15@1626.77,1260.24 ; v1(1611,1339) U5.R15@1626.77,1323.23 ; U5.F14@1658.27,1039.76 v1(1642.5,1055.5) U5.G14@1658.27,1071.26 ; U5.H14@1658.27,1102.76 v1(1642.5,1118.5) U5.J14@1658.27,1134.25 ; U5.K14@1658.27,1165.75 v1(1674,1181.5) U5.L14@1658.27,1197.24 ; v1(1674,1307.5) U5.P13@1689.76,1291.73 ; U5.E13@1689.76,1008.27 v1(1705.5,992.5) ; v1(1705.5,992.5) U5.E12@1721.26,1008.27 v1(1737,992.5) U5.E11@1752.76,1008.27 v1(1768.5,1024) U5.E10@1784.25,1008.27 ; v1(1705.5,1307.5) U5.P12@1721.26,1291.73 ; U5.P11@1752.76,1291.73 v1(1768.5,1307.5) U5.P10@1784.25,1291.73 ; U5.P8@1847.24,1291.73 U5.P7@1878.74,1291.73 v1(1894.49,1307.48) ; U5.P6@1910.24,1291.73 v1(1926,1307.5) ; U5.N5@1941.73,1260.24 v1(1957.5,1244.5) ; U5.P5@1941.73,1291.73 v1(1957.5,1307.5)
  TOP w15: R3.1@1025,882.5 R4.1@1062.5,882.5 ; v1(1062.5,910) R4.1@1062.5,882.5 ; C37.1@1100,882.5 R4.1@1062.5,882.5 ; Y4.4@1555,1668 1555,1692.5 v1(1562.5,1700) ; U3.5@1561.91,1843.31 1561.91,1801.18 v1(1562.5,1800.59) ; v1(1775,400) C27.1@1775,430 ; v1(2225,1800) C57.2@2225,1830 ; v1(2862.5,1800) C61.2@2862.5,1830
  LYR4 w15: v1(2787.5,1800) 2762.5,1775 2762.5,1557.5 2887.5,1432.5 2887.5,877.5 2960,805 3243.9,805 v1(3273.9,775)
  BOTTOM w10: v1(1775,400) 1775,411.6 ; U6.8@1842,411.6 1775,411.6 ; U6.7@1842,437.2 1775,437.2 ; U6.6@1842,462.8 1782.8,462.8 1775,455 1775,437.2 ; 1775,411.6 1775,437.2
  BOTTOM w12: C87.1@1520.75,1213 1543.88,1213 1567.36,1236.48 1571.48,1236.48 v1(1611,1276) ; C70.2@1638.25,1024 1642.5,1028.25 v1(1642.5,1055.5) 1642.5,1082.75 1638.25,1087 1642.5,1091.25 v1(1642.5,1118.5) ; v1(1674,1181.5) 1678.25,1185.75 C66.1@1678.25,1213 ; v1(1768.5,1024) 1788.5,1004 C72.2@1800,1003.98 ; v1(1768.5,1307.5) 1795.75,1334.75 C56.2@1800,1334.75
  BOTTOM w15: C15.2@862.5,710 862.5,740 880.25,757.75 v1(880.25,772.62) ; R1.1@912.5,882.5 v1(912.5,910) ; R156.1@987.5,842.5 C152.1@1025,842.5 1062.5,842.5 ; v1(1062.5,910) 1062.5,842.5 ; U7.4@1111.5,825 1080,825 1062.5,842.5 ; R14.1@1157.5,475 v1(1187.5,475) ; C38.1@1370,1362.5 C67.1@1370,1400 ; v1(1400,1400) C67.1@1370,1400 ; v1(1420.5,1450) 1397.5,1450 C77.1@1385,1462.5 ; v1(1420.5,1480) 1402.5,1480 C77.1@1385,1462.5 ; v1(1450,1450) C71.2@1480,1450 ; C159.1@1562.5,1670 v1(1562.5,1700) ; v1(1562.5,1800.59) C158.1@1562.5,1830 ; C59.1@1712.5,795 v1(1712.5,825) ; v1(1957.5,1244.5) 1961.75,1248.75 C73.2@1961.75,1276 ; v1(2225,1800) C75.2@2225,1830 R56.1@2262.5,1830 R55.1@2300,1830 ; v1(2300,1800) R55.1@2300,1830 ; v1(2712.5,1800) R67.1@2712.5,1830 ; v1(2787.5,1800) R69.1@2787.5,1830 ; v1(2862.5,1800) C76.2@2862.5,1830 R70.1@2825,1830 R69.1@2787.5,1830 ; R52.1@3273.9,745 v1(3273.9,775) ; C67.1@1370,1400 1370,1447.5 C77.1@1385,1462.5 ; R55.1@2300,1830 R59.1@2337.5,1830 R57.1@2375,1830 R58.1@2412.5,1830 R60.1@2450,1830 R61.1@2487.5,1830 R62.1@2525,1830 R63.1@2562.5,1830 R64.1@2600,1830 R65.1@2637.5,1830 R66.1@2675,1830 R67.1@2712.5,1830 ; R67.1@2712.5,1830 R68.1@2750,1830 R69.1@2787.5,1830
VDD_3V3AUX: C18.1 D1.2 U2.1 U4.1 | length 999.3
  TOP w4.75: D1.2@182.5,625 v1(220,625) ; C18.1@657.5,725 v1(740,725) 755,725 778.94,701.06 U2.1@778.94,686.61
  LYR3 w5.25: v1(220,625) 220,670 250,700 415,700 440,725 v1(740,725)
  BOTTOM w4.75: v1(220,625) 270,575 U4.1@427.5,575
VDD_3V3B: C20.1 C29.1 C126.2 C127.1 C128.1 C129.1 C130.1 C135.1 C153.1 C154.1 C155.2 FB4.1 P2.5 P9.3 P9.4 P10.4 R11.1 R23.1 R24.1 R101.1 R102.1 R103.1 R104.1 R105.1 R106.1 R107.1 R108.1 R109.1 R110.1 R111.1 R112.2 R113.2 R114.2 R119.1 R150.1 R151.1 R152.1 R153.1 R154.1 R155.1 R157.2 R158.1 R163.1 R166.2 U4.3 U13.C6 U13.E6 U13.F5 U13.J10 U13.K9 U13.M4 U13.N4 U13.P3 U13.P5 U14.12 U15.7 U15.8 | length 4839.4
  TOP w8: v3(1025,1699.21) U13.P5@1047.05,1699.21 ; v3(1025,1738.58) U13.P3@1047.05,1738.58 ; v3(1056.89,1728.74) U13.N4@1066.73,1718.9 ; U13.M4@1086.42,1718.9 v3(1106.1,1718.9) ; v3(1106.1,1620.47) U13.K9@1125.79,1620.47 ; v3(1145.47,1580) U13.J10@1145.47,1600.79 ; U13.F5@1204.53,1699.21 v3(1204.53,1718.9) ; U13.E6@1224.21,1679.53 v3(1243.9,1679.53) U13.C6@1263.58,1679.53
  TOP w10: U14.12@1086.5,1215.15 1102.34,1215.16 v1(1120,1215.16)
  TOP w15: R119.1@1220,1325 v1(1250,1325) ; C29.1@1350,357.5 v1(1350,387.5) 1372.5,410 1450,410 1475,435 1475,497.5 1465,507.5 R23.1@1450,507.5 R24.1@1450,555 ; v1(1350,1700) 1350,1655 1430,1575 1487.5,1575 v1(1550,1512.5) ; v1(2787.5,1680) R157.2@2825,1680 ; R166.2@2875,1030 2920,1030 v1(2930,1020) ; v1(3200,1610) R150.1@3200,1640 R155.1@3237.5,1640 R151.1@3275,1640 v1(3275,1610) 3290,1610 3300,1600 3300,1474.75 3290.25,1465 C154.1@3275,1465 3215,1465 C153.1@3200,1450 v1(3200,1360) R154.1@3200,1330 R153.1@3237.5,1330 R152.1@3275,1330 v1(3275,1360)
  LYR3 w15: v1(1350,387.5) 1379.14,358.36 1618.36,358.36 1685,425 2155,425 v1(2180,400)
  LYR4 w15: v1(2070,585) 2070,510 v1(2180,400)
  LYR5_PWR w35: 846.12,103.88 P9.3@875,75 903.88,103.88 ; 846.12,146.12 P9.4@875,175 ; 846.12,203.88 P9.4@875,175 ; 903.88,146.12 P9.4@875,175 ; 903.88,203.88 P9.4@875,175
  BOTTOM w7.5: v1(1120,1215.16) 1136.09,1231.25 1215,1231.25 1220,1226.25 R112.2@1220,1212.5
  BOTTOM w10: C127.1@1000,1670 1000,1690 1009.21,1699.21 v3(1025,1699.21) ; v3(1106.1,1620.47) 1125,1620.47 1134.53,1630 C128.1@1150,1630 1150,1604.53 1145.47,1600 v3(1145.47,1580) ; v3(1204.53,1718.9) 1204.53,1700 1200,1695.47 C129.1@1200,1670 1215.47,1670 1225,1679.53 v3(1243.9,1679.53) ; C130.1@1350,1670 v1(1350,1700) ; U15.8@2128,420.5 2170.5,420.5 C155.2@2180,430 2169.8,440.2 U15.7@2128,440.2
  BOTTOM w15: R11.1@305,725 305,710 315,700 335,700 345,690 C20.1@345,675 v1(375,675) U4.3@427.5,675 ; C126.2@925,1685 v1(925,1730) ; v1(925,1800) R107.1@925,1830 ; v1(975,1800) R108.1@975,1830 ; v1(1025,1800) R103.1@1025,1830 ; C135.1@1030,1325 1030,1305.16 v1(1120,1215.16) ; v1(1075,1800) R104.1@1075,1830 ; R111.1@1150,1870 v1(1150,1900) ; R114.2@1220,1175 R112.2@1220,1212.5 ; R113.2@1220,1325 v1(1250,1325) ; P2.5@1281,387.5 v1(1350,387.5) ; R158.1@1520,1512.5 v1(1550,1512.5) ; v1(1675,1800) R109.1@1675,1830 ; v1(1725,1800) R106.1@1725,1830 ; v1(1775,1800) R110.1@1775,1830 ; v1(1825,1800) R102.1@1825,1830 ; v1(1875,1800) R105.1@1875,1830 ; R163.1@1887.5,617.5 1887.5,572.5 1900,560 2045,560 v1(2070,585) ; v1(1925,1800) R101.1@1925,1830 ; v1(2180,400) C155.2@2180,430 ; v1(3275,1610) 3295.86,1630.86 3295.86,1731.15 3295.09,1731.92 P10.4@3295.09,1770.72
  BOTTOM w30: P9.3@875,75 P9.4@875,175
  other v1: 1012.5,1412.5
VDD_5V: C2.2 P1.1 P9.5 P9.6 U2.10 | length 1002.4
  TOP w8: 745,544.88 U2.10@778.94,544.88
  LYR4 w30: P1.1@440,375 440,265 465,240 910,240 P9.6@975,175
  BOTTOM w25: C2.2@360,490 425,490 440,475 P1.1@440,375
  BOTTOM w30: P9.5@975,75 P9.6@975,175
VDD_ADC: C93.1 FB2.1 P9.32 R27.1 U5.D8 | length 1240.8
  TOP w10: U5.D8@1847.24,976.77 v1(1862.99,961.02)
  TOP w15: v1(1805,725) 1800,720 C93.1@1775,720 1775,761.25 R27.1@1776.25,762.5 1804.75,791 1804.75,824.75 v1(1805,825)
  LYR3 w15: v1(1805,825) 1805,970 1820,985 1839.01,985 v1(1862.99,961.02)
  LYR4 w15: v1(1805,725) 1805,695 2130,370 2210,370 2250,330 2250,200 P9.32@2275,175
  BOTTOM w15: v1(1805,725) 1805,695 1825,675 FB2.1@1825,674.9
VDD_CORE: C11.2 C39.2 C40.2 C41.1 C42.1 C43.1 C44.1 C45.1 C46.1 C47.1 C48.1 C49.1 C50.1 C51.1 C52.1 C53.1 C54.1 C55.2 L3.2 U2.29 U5.F6 U5.F7 U5.G6 U5.G7 U5.G10 U5.H11 U5.J12 U5.K6 U5.K8 U5.K12 U5.L6 U5.L7 U5.L8 U5.L9 U5.M11 U5.M13 U5.N8 U5.N9 U5.N12 U5.N13 | length 2260.8
  TOP w10: v1(1674,1244.5) U5.M13@1689.76,1228.74 ; U5.N13@1689.76,1260.24 v1(1705.5,1244.5) U5.N12@1721.24,1260.24 ; v1(1705.5,1118.5) U5.J12@1721.26,1134.25 ; U5.K12@1721.26,1165.75 v1(1737,1181.5) ; v1(1737,1087) U5.H11@1752.76,1102.76 ; U5.M11@1752.76,1228.74 v1(1768.5,1213) ; v1(1768.5,1087) U5.G10@1784.24,1071.26 ; U5.L9@1815.75,1197.24 v1(1831.5,1212.99) ; U5.N9@1815.75,1260.24 v1(1831.5,1275.98) U5.N8@1847.24,1260.24 ; U5.K8@1847.24,1165.75 v1(1862.99,1181.5) U5.L7@1878.74,1197.24 ; U5.L8@1847.24,1197.24 v1(1862.99,1212.99) ; U5.F7@1878.74,1039.76 v1(1894.5,1024) ; U5.G7@1878.74,1071.26 v1(1894.5,1055.5) ; U5.F6@1910.24,1039.76 v1(1926,1055.5) U5.G6@1910.24,1071.26 ; U5.K6@1910.24,1165.75 v1(1926,1181.5) U5.L6@1910.24,1197.24
  LYR4 w20: v1(1125,515) v1(1150,515) 1225,590 1225,740 1210,755 1210,905 1225,920 1225,975 1240,990 1265,990 ; v1(1265,975) 1265,990 ; v1(1265,1000) 1265,990
  BOTTOM w12: C45.1@1520.75,1173.63 1524.62,1177.5 1532.5,1177.5 1568,1213 v1(1579.5,1213) ; C41.1@1678.25,1276 1674,1271.75 v1(1674,1244.5) v1(1705.5,1244.5) ; v1(1737,1087) v1(1705.5,1118.5) 1717,1130 1717,1150 1717,1161.5 v1(1737,1181.5) ; v1(1768.5,1087) 1772.75,1082.75 C49.1@1800,1082.75 ; v1(1768.5,1213) 1795.75,1213 C47.1@1800,1217.25 1804.26,1212.99 v1(1831.5,1212.99) ; C42.1@1800,1296 1804.25,1291.75 1815.73,1291.75 v1(1831.5,1275.98) ; C48.1@1843,1150 1847.25,1154.25 1847.25,1165.76 v1(1862.99,1181.5) v1(1926,1181.5) ; C50.1@1863,1019.75 1867.25,1024 v1(1894.5,1024) v1(1894.5,1055.5) v1(1926,1055.5) ; v1(1862.99,1212.99) C43.1@1863,1240.25
  BOTTOM w15: C53.1@1370,950 1370,990 C39.2@1385,1005 ; C51.1@1370,1175 1370,1135 C40.2@1385,1120 ; C44.1@1520.75,1016.13 1520.75,1055.5 v1(1548,1055.5) ; C52.1@1370,1062.5 1400,1062.5 ; C52.1@1370,1062.5 1370,1105 C40.2@1385,1120 ; C52.1@1370,1062.5 1370,1020 C39.2@1385,1005 ; C39.2@1385,1005 1400,1020 v1(1400,1047.5) 1400,1062.5 ; C40.2@1385,1120 1400,1105 v1(1400,1077.5) 1400,1062.5 ; v1(1125,515) v1(1150,515) 1150,542.5 L3.2@1137.5,555 1125,542.5 v1(1125,515)
VDD_MPU: C12.2 C62.2 C63.1 C64.1 C65.1 L2.2 U2.24 U5.F10 U5.F11 U5.F12 U5.F13 U5.G13 U5.H13 U5.J13 | length 1350.9
  TOP w10: U5.J13@1689.76,1134.25 v1(1674,1118.5) U5.H13@1689.76,1102.76 1685.5,1098.5 1685.5,1075.52 U5.G13@1689.76,1071.26 v1(1674,1055.5) U5.F13@1689.76,1039.76 v1(1705.5,1024) U5.F12@1721.26,1039.76 U5.F11@1752.76,1039.76 1755.36,1042.36 1781.64,1042.36 U5.F10@1784.24,1039.76
  TOP w20: v1(1420.5,845) 1420.5,854 v1(1420.5,870)
  TOP w25: 1035,445 1230,445 1305,520 1305,680 1355,730 1355,825 1384,854 1420.5,854
  BOTTOM w12: v1(1705.5,1024) 1709.75,1019.75 C63.1@1737,1019.75
  BOTTOM w15: C64.1@1370,787.5 1370,835 C62.2@1385,850 ; v1(1674,1118.5) 1678.25,1122.75 C65.1@1678.25,1150 ; C62.2@1385,850 1390,845 v1(1420.5,845) v1(1420.5,870) 1395,870 1385,860 C62.2@1385,850 ; L2.2@1042.5,350 v1(1042.5,390) v1(1067.5,390) 1067.5,350 L2.2@1055,337.5 L2.2@1042.5,350
VDD_MPUON: TP2.1 U5.A2 | length 419.2
  TOP w4.75: U5.A2@2036.22,882.28 2036.22,813.78 2060,790 2060,760 2075,745 2100,745 2150,695 2150,655 2165,640 2187.74,640 2215.24,612.5 TP2.1@2262.5,612.5
VDD_PHYA: C131.1 C132.1 C133.2 FB4.2 R120.2 R121.2 R122.2 R123.2 R137.2 U14.1 U14.27 | length 713.9
  TOP w10: v1(837.5,1300) 837.5,1290 857.5,1270 857.5,1263 865.95,1254.55 U14.27@888.5,1254.55 ; v1(905,1090) 918.55,1103.55 U14.1@918.55,1126
  BOTTOM w15: v1(420,1150) R137.2@455,1150 ; v1(737.5,1150) R120.2@767.5,1150 ; v1(737.5,1187.5) R121.2@767.5,1187.5 ; v1(737.5,1225) R122.2@767.5,1225 ; v1(737.5,1262.5) R123.2@767.5,1262.5 ; v1(837.5,1300) 877.5,1300 C133.2@890,1312.5 ; v1(837.5,1412.5) FB4.2@887.6,1412.5 890,1410.1 C133.2@890,1312.5 ; v1(905,1090) C131.1@905,1125 C132.1@905,1175 905,1220 890,1235 C133.2@890,1312.5
VDD_PLL: C79.1 C92.1 C94.1 C106.1 FB1.2 U5.E7 U5.H15 U5.R10 U5.R11 | length 590.1
  TOP w10: v1(1611,1087) U5.H15@1626.77,1102.76 ; v1(1737,1307.5) U5.R11@1752.76,1323.23 v1(1768.5,1339) 1784.25,1323.72 U5.R10@1784.25,1323.23 ; U5.E7@1878.74,1008.27 v1(1894.49,992.52)
  LYR3 w15: v1(1516.5,1244.5) 1538.5,1222.5 1555.51,1222.5 1568.86,1235.85 1568.86,1245 1579,1255.14 1619.65,1255.14 1622.65,1258.14 1623.14,1258.14 1640,1275 1704.5,1275 v1(1737,1307.5) v1(1768.5,1339)
  BOTTOM w12: C94.1@1737,1280.25 v1(1737,1307.5)
  BOTTOM w25: FB1.2@1387.4,1262.5 1427.5,1262.5 1445.5,1244.5 v1(1516.5,1244.5)
VDD_RTC: C104.1 U5.D6 | length 211.7
  TOP w10: U5.D6@1910.24,976.77 v1(1926,961)
  BOTTOM w4.75: v1(1926,961) 1941.75,945.25 1941.75,926.75 1941.74,900 1919.3,877.56 1919.3,813.2 C104.1@1937.5,795
VDDS: C80.1 C81.1 C82.1 C83.1 C84.1 C85.1 R8.2 R9.1 U5.E6 U5.E14 U5.F9 U5.K13 U5.N6 U5.P9 U5.P14 | length 2231.6
  TOP w10: v1(1642.5,992.5) U5.E14@1658.27,1008.27 ; v1(1642.5,1307.5) U5.P14@1658.27,1291.73 ; U5.K13@1689.76,1165.75 v1(1705.5,1181.5) ; U5.F9@1815.75,1039.76 v1(1831.5,1024.02) ; U5.P9@1815.75,1291.73 v1(1831.5,1307.48) ; v1(1894.5,1244.5) U5.N6@1910.24,1260.24 ; U5.E6@1910.24,1008.27 v1(1926,992.5)
  TOP w15: R8.2@430,675 R9.1@430,725 430,770
  LYR5_PWR w12: v1(1705.5,1181.5) 1724.86,1162.14 1787.86,1162.14 v1(1800,1150)
  BOTTOM w4.75: 1561.76,1291.76 1617.52,1291.76 1620.76,1295 1630,1295 v1(1642.5,1307.5) ; 1626.74,1323.26 1626.74,1388.26
  BOTTOM w10: C84.1@1520.75,1276 1546,1276 1561.76,1291.76 ; 1626.74,1323.26 v1(1642.5,1307.5)
  BOTTOM w12: 1626.74,1388.26 1626.74,1413.72 ; 1626.77,1413.75 C80.1@1626.77,1429.25
  BOTTOM w15: 430,770 430.25,769.75 489.75,769.75 670,950 1110,950 1125,935 1270,935 1300,905 1430,905 1489.36,845.64 1530.64,845.64 1545,860 1545,895 ; C80.1@1626.77,1429.25 1639.25,1429.25 1650,1440 1650,1485.43 1664.57,1500 1735,1500 1755.86,1479.14 1815.86,1479.14 1830,1465 1830,1440 1840.75,1429.25 C81.1@1863,1429.25
  other v1: 1579.5,1024
VDDS_DDR: C9.2 C95.2 C96.2 C97.1 C98.1 C99.1 C100.1 C101.1 C102.1 C103.1 C107.1 C108.1 C109.1 C110.1 C111.1 C112.1 C113.1 C114.1 C115.1 C116.1 C117.1 C118.2 C119.1 C120.1 C121.1 C122.2 R6.2 R97.1 R98.1 U5.E5 U5.F5 U5.G5 U5.H5 U5.J5 U5.K5 U5.L5 U12.A1 U12.A8 U12.B2 U12.C1 U12.C9 U12.D2 U12.D9 U12.E9 U12.F1 U12.G7 U12.H2 U12.H9 U12.K2 U12.K8 U12.N1 U12.N9 U12.R1 U12.R9 | length 1820
  TOP w10: U5.E5@1941.73,1008.27 U5.F5@1941.73,1039.76 v1(1957.5,1055.5) U5.G5@1941.73,1071.26 ; U5.H5@1941.73,1102.76 v1(1957.5,1118.5) U5.J5@1941.73,1134.25 ; U5.K5@1941.73,1165.75 v1(1957.5,1181.5) U5.L5@1941.73,1197.24
  TOP w15: C96.2@2180,575 v1(2180,622.5) ; v1(792.5,280) 792.5,317.5 C9.2@812.5,337.5 817.5,332.5 v1(817.5,280) v1(792.5,280)
  BOTTOM w12: C100.1@1961.75,1024 1957.5,1028.25 v1(1957.5,1055.5) 1957.5,1082.75 1961.75,1087 1957.5,1091.25 v1(1957.5,1118.5) 1957.5,1145.75 C98.1@1961.72,1150 1957.5,1154.25 v1(1957.5,1181.5) 1957.5,1208.75 C97.1@1961.75,1213
  BOTTOM w15: R6.2@740,320 740,295 755,280 v1(792.5,280) v1(817.5,280) ; C101.1@2050,795 2055,800 v1(2080,800) ; C102.1@2100,617.5 C103.1@2150,617.5 2175,617.5 v1(2180,622.5) ; C113.1@2320,754.5 v1(2358.25,754.5) ; C112.1@2320,817.5 v1(2358.25,817.5) ; C111.1@2320,912 2342,890 2367.75,890 v1(2389.75,912) ; C110.1@2320,1006.5 2343.5,1030 2366.25,1030 v1(2389.75,1006.5) ; C109.1@2320,1069.5 v1(2358.25,1069.5) ; C108.1@2320,1164 v1(2358.25,1164) ; C107.1@2320,1227 v1(2358.25,1227) ; v1(2520,723) R97.1@2520,754.5 ; R98.1@2520,1006.5 2547.25,1006.5 v1(2578.75,1038) ; v1(2600,662.5) C122.2@2640,662.5 ; v1(2600,1287.5) C118.2@2640,1287.5 ; v1(2610.25,912) 2657.5,959.25 C119.1@2680,959.25 ; v1(2610.25,1227) C114.1@2680,1227 ; v1(2641.75,754.5) C121.1@2680,754.5 ; v1(2641.75,817.5) C120.1@2680,817.5 ; v1(2641.75,1006.5) C117.1@2680,1006.5 ; v1(2641.75,1101) C116.1@2680,1101 ; v1(2641.75,1164) C115.1@2680,1164 ; v1(2080,800) v1(2080,770) 2110,770 C95.2@2125,785 2110,800 v1(2080,800)
  other v1: 1965,235 1990,235 2115,235 2140,235 2280,235 2310,235 2340,235 2421.25,1101 2641.75,1132.5 2389.75,1195.5
VIO: R7.2 U2.18 | length 577.9
  TOP w4.75: R7.2@430,625 430,605 465,570 v1(500,570) ; v1(870,440) 872.5,440 892.13,459.63 U2.18@892.13,478.94
  LYR4 w5.25: v1(500,570) 620,570 730.99,459.01 850.99,459.01 v1(870,440)
VLDO1: R5.1 R7.1 R8.1 U2.3 | length 418.2
  TOP w8: 725.12,655.12 U2.3@778.94,655.12
  TOP w15: R8.1@470,675 R7.1@470,625 470,605 480,595 645,595 657.5,607.5 R5.1@657.5,625 695,625 725.12,655.12
VREFP_ADC: C31.1 C32.1 C33.1 R27.2 U5.B9 | length 302.2
  TOP w4.75: 1795,855 1800,860 1800,898.03
  TOP w10: 1800,898.03 U5.B9@1815.75,913.78
  TOP w12: 1783.13,843.13 1795,855
  TOP w15: C32.1@1662.5,720 C31.1@1700,720 C33.1@1737.5,720 1736.25,721.25 R27.2@1736.25,762.5 1736.25,769.11 1780,812.86 1780,840 1783.13,843.13
VRTC: C16.1 C105.1 R5.2 R26.1 U5.D7 | length 1652
  TOP w10: U5.D7@1878.74,976.77 v1(1894.5,961)
  TOP w15: R5.2@617.5,625 617.5,645 627.5,655 647.5,655 657.5,665 C16.1@657.5,687.5 692.5,687.5 v1(710,705)
  LYR3 w15: v1(740,830) 795,885 1335,885 1400,820 1520,820 1565.86,774.14 1604.14,774.14 1615,785 1825,785 1862.5,822.5 v1(1862.5,825)
  LYR4 w15: v1(710,705) 710,800 v1(740,830)
  BOTTOM w7: v1(1937.5,825) 1945,825 1956.25,813.74 1956.25,760 1961.25,755 R26.1@1975,755
  BOTTOM w15: C105.1@1862.5,795 v1(1862.5,825)
WAKEUP: R26.2 U2.13 U5.C5 | length 2370.9
  TOP w4.75: U2.13@813.39,478.94 813.39,441.61 v1(815,440) ; U5.C5@1941.73,945.28 v1(1957.5,929.5)
  LYR3 w5.25: v1(815,440) 835,420 910,420 960,370 1170,370 1220,320 1610,320 1660,370 2200,370 2225,395 2225,440 v1(2245,460)
  LYR4 w5.25: v1(1957.5,929.5) 1940,912 1940,887.61 2064.01,763.6 2064.01,763.38 2073.38,754.01 2073.6,754.01 2160,667.61 2160,545 v1(2245,460)
  BOTTOM w4.75: v1(1957.5,929.5) 1973.26,913.74 1973.26,887.5 1975,885.76 R26.2@1975,795
WP: R156.2 TP4.1 U7.5 | length 1123.1
  BOTTOM w4.75: TP4.1@150,750 505,750 680.74,925.74 959,925.74 969,915.74 969,887.5 974,882.5 R156.2@987.5,882.5 1001,882.5 1006,887.5 1006,915.74 1016,925.74 1101.5,925.74 1111.5,915.74 U7.5@1111.5,900
XDMA_EVENT_INTR0: P2.17 R18.2 U6.1 | length 644.7
  BOTTOM w4.75: P2.17@1281,687.5 1347.5,687.5 1375,660 1375,605 1417.5,562.5 1593.71,562.5 1668.38,487.83 1668.38,434 1664.38,430 R18.2@1650,430 1650,425 1663.4,411.6 U6.1@1708,411.6
YEL_C: P5.11 R130.2 | length 124.7
  TOP w4.75: P5.11@132,1026 170,1064 v1(170,1100)
  BOTTOM w4.75: v1(170,1100) R130.2@205,1100
YELA: P5.12 R135.1 U14.2 | length 1093.8
  TOP w4.75: v1(932.5,1090) 938.25,1095.75 U14.2@938.25,1126
  LYR3 w5.25: P5.12@192,926 192,957 280,1045 475,1045 575,945 700,945 830,1075 855,1075 890,1110 912.5,1110 v1(932.5,1090)
  BOTTOM w4.75: P5.12@192,926 192,975 205,988 R135.1@205,1050
ZQ: R99.2 U12.L8 | length 76.3
  BOTTOM w4.75: v1(2610.25,880.5) 2626,864.75 R99.2@2680,864.75
pads on no net: "P5. " D6.6 D6.7 D6.9 D6.10 D7.6 D7.7 D7.9 D7.10 J1.2 J1.3 J1.6 P1.3 P2.6 P5.7 P6.2 U2.14 U2.15 U2.16 U2.17 U2.33 U2.34 U2.35 U2.36 U2.37 U2.38 U2.44 U3.1 U5.E17 U5.E18 U5.F16 U5.M5 U5.M15 U5.P18 U9.3 U9.5 U10.5 U11.26 U11.28 U12.J1 U12.J9 U12.L1 U12.L9 U13.A1 U13.A2 U13.A6 U13.A7 U13.A8 U13.A9 U13.A10 U13.A11 U13.A12 U13.A13 U13.A14 U13.B1 U13.B7 U13.B8 U13.B9 U13.B10 U13.B11 U13.B12 U13.B13 U13.B14 U13.C1 U13.C3 U13.C5 U13.C7 U13.C8 U13.C9 U13.C10 U13.C11 U13.C12 U13.C13 U13.C14 U13.D1 U13.D2 U13.D3 U13.D4 U13.D12 U13.D13 U13.D14 U13.E1 U13.E2 U13.E3 U13.E5 U13.E8 U13.E9 U13.E10 U13.E12 U13.E13 U13.E14 U13.F1 U13.F2 U13.F3 U13.F10 U13.F12 U13.F13 U13.F14 U13.G1 U13.G2 U13.G3 U13.G10 U13.G12 U13.G13 U13.G14 U13.H1 U13.H2 U13.H3 U13.H5 U13.H12 U13.H13 U13.H14 U13.J1 U13.J2 U13.J3 U13.J5 U13.J12 U13.J13 U13.J14 U13.K1 U13.K2 U13.K3 U13.K6 U13.K7 U13.K10 U13.K12 U13.K13 U13.K14 U13.L1 U13.L2 U13.L3 U13.L12 U13.L13 U13.L14 U13.M1 U13.M2 U13.M3 U13.M7 U13.M8 U13.M9 U13.M10 U13.M11 U13.M12 U13.M13 U13.M14 U13.N1 U13.N3 U13.N6 U13.N7 U13.N8 U13.N9 U13.N10 U13.N11 U13.N12 U13.N13 U13.N14 U13.P1 U13.P2 U13.P7 U13.P8 U13.P9 U13.P10 U13.P11 U13.P12 U13.P13 U13.P14 Y1.2 Y1.3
